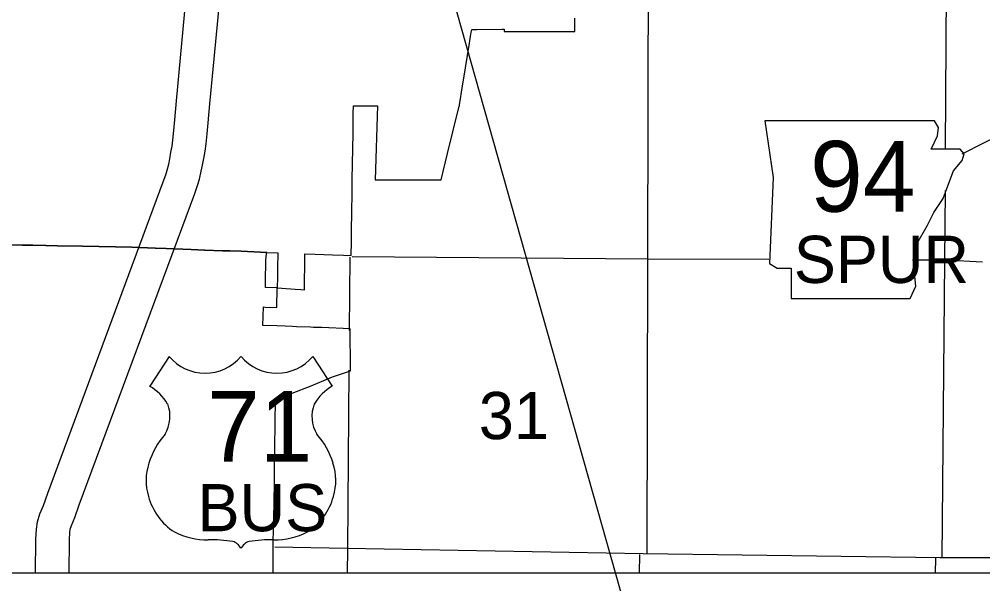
# Model space of a CAD drawing. Extents: x 309389.3 to 309420.2, y 336441.4 to 336461.2.
# Drawn here: x 309392.47 to 309393.778, y 336455.355 to 336456.121 of the extents above; entities that cross this region are included whole.
import ezdxf

# ---------------------------------------------------------------- set-up
doc = ezdxf.new("R2010")
doc.units = 0
for name, color, linetype in [('Level 4', 7, 'Continuous'), ('Level 48', 7, 'Continuous'), ('Level 62', 7, 'Continuous'), ('Level 63', 7, 'Continuous'), ('R_Axis Annot', 7, 'Continuous'), ('R_Contours', 7, 'Continuous'), ('R_Detour Annot', 7, 'Continuous'), ('R_MOT', 7, 'Continuous')]:
    doc.layers.add(name, color=color, linetype=linetype)

msp = doc.modelspace()

# ---------------------------------------------------------------- linework, layer by layer
at = {"layer": 'Level 4'}
for points in [[(309393.3235, 336456.4578), (309393.3236, 336456.201), (309393.3228, 336455.7953), (309393.322, 336455.3953)], [(309393.7274, 336455.9452), (309393.7287, 336456.1596)], [(309393.7227, 336455.3899), (309393.7265, 336455.7936), (309393.7271, 336455.8882)], [(309392.9189, 336455.7989), (309392.9187, 336455.7989)], [(309392.922, 336455.7989), (309393.3232, 336455.7957), (309393.4875, 336455.7951)], [(309393.6827, 336455.7943), (309393.7264, 336455.7942), (309393.7777, 336455.7916)], [(309393.312, 336455.3949), (309393.3117, 336455.3696)], [(309393.7138, 336455.3696), (309393.714, 336455.3896)]]:
    msp.add_lwpolyline(points, dxfattribs=at)
at = {"layer": 'Level 48'}
for points in [[(309392.9189, 336455.7978), (309392.9181, 336455.6984)], [(309392.9176, 336455.6447), (309392.9156, 336455.4024), (309392.9152, 336455.3696)], [(309393.9519, 336455.3902), (309393.7199, 336455.3902), (309393.3171, 336455.3959), (309392.9152, 336455.403), (309392.8169, 336455.4049)]]:
    msp.add_lwpolyline(points, dxfattribs=at)
at = {"layer": 'Level 62'}
for points in [[(309392.9222, 336455.9012), (309392.9222, 336455.9031), (309392.9232, 336455.966), (309392.9235, 336455.9844), (309392.9235, 336455.9844), (309392.9236, 336455.9926), (309392.9236, 336455.9957), (309392.9237, 336456.0007), (309392.9238, 336456.0032), (309392.9264, 336456.0032), (309392.9347, 336456.0032), (309392.9396, 336456.0032), (309392.9446, 336456.0032), (309392.9495, 336456.0032), (309392.9543, 336456.0032), (309392.9562, 336456.0032), (309392.9532, 336455.903), (309393.0025, 336455.9028), (309393.0185, 336455.9027), (309393.0249, 336455.9029), (309393.0429, 336455.9027), (309393.0516, 336455.9385), (309393.0588, 336455.9681), (309393.0672, 336456.0028), (309393.0675, 336456.0028), (309393.0678, 336456.005), (309393.069, 336456.0129), (309393.0704, 336456.0216), (309393.0758, 336456.0547), (309393.0811, 336456.0881), (309393.0832, 336456.1004), (309393.0835, 336456.102), (309393.0836, 336456.1027), (309393.084, 336456.1051), (309393.0843, 336456.1069), (309393.0856, 336456.1069), (309393.089, 336456.1069), (309393.0914, 336456.1069), (309393.125, 336456.1071), (309393.1282, 336456.1072), (309393.1282, 336456.1041), (309393.2243, 336456.1041), (309393.2244, 336456.1178), (309393.2244, 336456.1223)], [(309392.4207, 336455.8154), (309392.474, 336455.8143), (309392.4742, 336455.8144), (309392.4888, 336455.8141), (309392.5064, 336455.8138), (309392.5221, 336455.8134), (309392.5561, 336455.8128), (309392.6228, 336455.8115), (309392.6548, 336455.8102), (309392.6551, 336455.8102), (309392.6698, 336455.8096), (309392.7036, 336455.8083), (309392.7216, 336455.8076), (309392.7219, 336455.8076), (309392.7462, 336455.8067), (309392.7562, 336455.8065), (309392.7712, 336455.8059), (309392.8061, 336455.8045), (309392.8211, 336455.8039), (309392.821, 336455.8002), (309392.8208, 336455.7868), (309392.8206, 336455.7708), (309392.8204, 336455.7562), (309392.8264, 336455.7558), (309392.8447, 336455.7546), (309392.8525, 336455.7542), (309392.8572, 336455.7539), (309392.8574, 336455.769), (309392.8577, 336455.7837), (309392.8579, 336455.7989), (309392.858, 336455.8025), (309392.8717, 336455.802), (309392.8953, 336455.8011), (309392.9102, 336455.8006), (309392.9207, 336455.8001), (309392.9208, 336455.8041), (309392.9209, 336455.8148), (309392.9211, 336455.8276), (309392.9213, 336455.8402), (309392.9215, 336455.8531), (309392.9217, 336455.8657), (309392.9219, 336455.8784), (309392.9221, 336455.8909), (309392.9221, 336455.8957), (309392.9222, 336455.9012)], [(309392.8061, 336455.8045), (309392.7712, 336455.8059), (309392.7562, 336455.8065), (309392.7462, 336455.8067), (309392.7219, 336455.8076), (309392.7216, 336455.8076), (309392.7036, 336455.8083), (309392.6698, 336455.8096), (309392.6551, 336455.8102), (309392.6548, 336455.8102), (309392.6228, 336455.8115), (309392.5561, 336455.8128), (309392.5221, 336455.8134), (309392.5064, 336455.8138), (309392.4888, 336455.8141), (309392.4742, 336455.8144), (309392.474, 336455.8143), (309392.4207, 336455.8154)], [(309392.8204, 336455.7562), (309392.8043, 336455.7569), (309392.8045, 336455.7649), (309392.8046, 336455.7744), (309392.8047, 336455.7839), (309392.8048, 336455.7933), (309392.8056, 336455.8028), (309392.8061, 336455.8045)], [(309392.8146, 336455.3696), (309392.8149, 336455.4065), (309392.8154, 336455.4338), (309392.816, 336455.4619), (309392.8162, 336455.4758), (309392.8164, 336455.4824), (309392.8168, 336455.5067), (309392.8182, 336455.6056), (309392.8408, 336455.6135), (309392.8662, 336455.6235), (309392.8953, 336455.6355), (309392.9196, 336455.644), (309392.9196, 336455.6474), (309392.9193, 336455.701), (309392.8808, 336455.7024), (309392.8694, 336455.7028), (309392.8657, 336455.703), (309392.8467, 336455.7037), (309392.841, 336455.7039), (309392.8309, 336455.7043), (309392.8196, 336455.7047), (309392.8008, 336455.7054), (309392.8019, 336455.7305), (309392.804, 336455.7304), (309392.82, 336455.7298), (309392.8204, 336455.7562)]]:
    msp.add_lwpolyline(points, dxfattribs=at)
at = {"layer": 'Level 63'}
msp.add_line((309393.4111, 336454.9055), (309392.7786, 336457.1397), dxfattribs=at)
at = {"layer": 'R_Axis Annot'}
for points in [[(309392.4924, 336455.3696), (309392.4928, 336455.4157), (309392.4934, 336455.4292), (309392.495, 336455.4391), (309392.4982, 336455.4498), (309392.5032, 336455.4614), (309392.5089, 336455.4778), (309392.6657, 336455.9), (309392.669, 336455.9095), (309392.671, 336455.9159), (309392.673, 336455.9243), (309392.6745, 336455.9312), (309392.676, 336455.9403), (309392.6777, 336455.9486), (309392.6786, 336455.9568), (309392.6801, 336455.9697), (309392.6813, 336455.9842), (309392.6838, 336456.0102), (309392.6983, 336456.1659)], [(309392.5379, 336455.3696), (309392.5383, 336455.4145), (309392.5387, 336455.4245), (309392.5394, 336455.429), (309392.541, 336455.4343), (309392.5455, 336455.4449), (309392.5517, 336455.4623), (309392.7084, 336455.8845), (309392.7121, 336455.8951), (309392.7149, 336455.9039), (309392.7173, 336455.9144), (309392.7191, 336455.9226), (309392.7207, 336455.932), (309392.7226, 336455.9417), (309392.7237, 336455.9516), (309392.7253, 336455.9651), (309392.7266, 336455.9801), (309392.729, 336456.006), (309392.7436, 336456.1615)]]:
    msp.add_lwpolyline(points, dxfattribs=at)
at = {"layer": 'R_Contours'}
msp.add_line((309393.7498, 336455.9379), (309393.9487, 336456.0397), dxfattribs=at)
msp.add_lwpolyline([(309393.482, 336455.9828), (309393.4935, 336455.9059), (309393.4884, 336455.7893), (309393.4987, 336455.7829), (309393.5179, 336455.7829), (309393.5179, 336455.7419), (309393.6794, 336455.7419), (309393.6871, 336455.7585), (309393.6845, 336455.7854), (309393.6884, 336455.8162), (309393.7025, 336455.8406), (309393.7114, 336455.8585), (309393.7242, 336455.8777), (309393.7319, 336455.8982), (309393.7383, 336455.9149), (309393.7499, 336455.929), (309393.7524, 336455.938), (309393.7473, 336455.9444), (309393.7076, 336455.9444), (309393.7165, 336455.9623), (309393.7178, 336455.9738), (309393.7125, 336455.9827)], close=True, dxfattribs=at)
at = {"layer": 'R_Detour Annot'}
for p, q in [((309392.6736, 336455.6634), (309392.6474, 336455.6229)), ((309392.8686, 336455.6634), (309392.8948, 336455.6229))]:
    msp.add_line(p, q, dxfattribs=at)
for centre, radius, start, end in [((309392.7225, 336455.7045), 0.0638, 220.075, 319.6701), ((309392.8198, 336455.7045), 0.0638, 220.3299, 319.925), ((309392.6131, 336455.564), 0.0681, 30.7809, 59.9883), ((309392.9291, 336455.564), 0.0681, 120.0117, 149.2191), ((309392.6281, 336455.582), 0.0467, 328.8105, 21.2108), ((309392.9141, 336455.582), 0.0467, 158.7892, 211.1895), ((309392.7503, 336455.4862), 0.109, 138.9565, 162.6913), ((309392.792, 336455.4862), 0.109, 17.3087, 41.0435), ((309392.7143, 336455.4951), 0.072, 160.9576, 197.3819), ((309392.8279, 336455.4951), 0.072, 342.6181, 19.0424), ((309392.726, 336455.4953), 0.0833, 195.1074, 237.1312), ((309392.8162, 336455.4953), 0.0833, 302.8688, 344.8926), ((309392.7276, 336455.5216), 0.107, 244.0771, 269.5779), ((309392.8147, 336455.5216), 0.107, 270.4221, 295.9229), ((309392.73, 336455.2187), 0.196, 81.1942, 90.9539), ((309392.7545, 336455.3944), 0.0188, 28.0342, 72.9864), ((309392.7877, 336455.3944), 0.0188, 107.0136, 151.9658), ((309392.8122, 336455.2187), 0.196, 89.0461, 98.8058)]:
    msp.add_arc(centre, radius, start, end, dxfattribs=at)
at = {"layer": 'R_MOT'}
msp.add_lwpolyline([(309389.3351, 336459.8498), (309394.8545, 336459.8498), (309394.8545, 336455.3696), (309389.3351, 336455.3696)], close=True, dxfattribs=at)

# ---------------------------------------------------------------- texts
at = {"layer": 'Level 4'}
msp.add_text('31', height=0.064, dxfattribs=at).set_placement((309393.0939, 336455.5512))
at = {"layer": 'R_Contours'}
for s, height, p in [('94', 0.096, (309393.5435, 336455.8596)), ('SPUR', 0.064, (309393.5214, 336455.763))]:
    msp.add_text(s, height=height, dxfattribs=at).set_placement(p)
at = {"layer": 'R_Detour Annot'}
for s, height, p in [('71', 0.096, (309392.7252, 336455.5207)), ('BUS', 0.064, (309392.7122, 336455.4263))]:
    msp.add_text(s, height=height, dxfattribs=at).set_placement(p)

doc.saveas('drawing.dxf')
